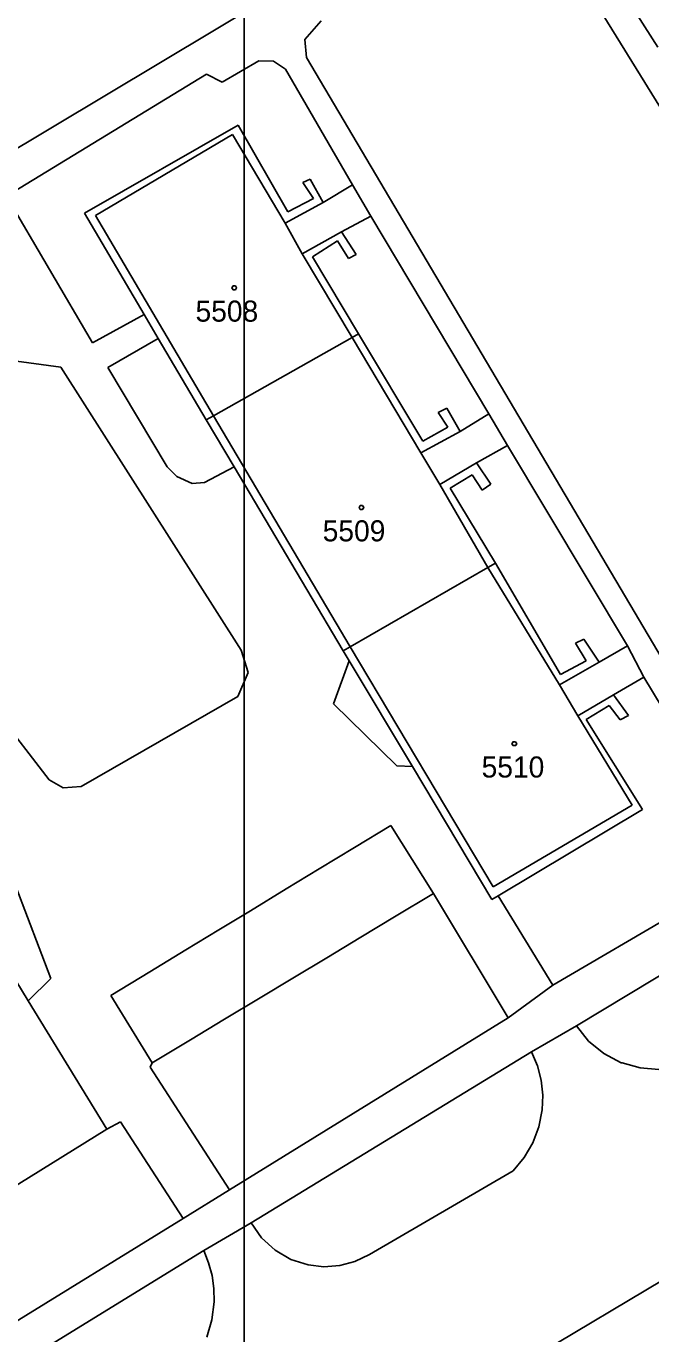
# Model space of a CAD drawing. Extents: x -263587 to -261993, y -1238795 to -1236748.
# Drawn here: x -263008.6 to -262961.1, y -1237443 to -1237343.7 of the extents above; entities that cross this region are included whole.
import ezdxf

# ---------------------------------------------------------------- set-up
doc = ezdxf.new("R2010")
doc.units = 0
doc.layers.add('Vrstva 1', color=7, linetype='Continuous')
doc.layers.add('Vrstva 51', color=7, linetype='Continuous')

msp = doc.modelspace()

# ---------------------------------------------------------------- linework, layer by layer
at = {"layer": 'Vrstva 1'}
for p, q in [((-262969.49, -1237335.2), (-262932.48, -1237395.21)), ((-263042.6, -1237372.96), (-262982.3, -1237336.84)), ((-262987.41, -1237344.72), (-262986.18, -1237343.32)), ((-262960.62, -1237345.3), (-262962.19, -1237342.85)), ((-262962.19, -1237342.85), (-262960.62, -1237345.3)), ((-262987.29, -1237346.1), (-262987.41, -1237344.72)), ((-262990.92, -1237346.35), (-262993.69, -1237347.98)), ((-262989.79, -1237346.37), (-262990.92, -1237346.35)), ((-262988.88, -1237346.97), (-262989.79, -1237346.37)), ((-262951.55, -1237406.53), (-262987.29, -1237346.1)), ((-262994.89, -1237347.35), (-263010.07, -1237356.63)), ((-262993.69, -1237347.98), (-262994.89, -1237347.35)), ((-262983.81, -1237355.75), (-262988.88, -1237346.97)), ((-263004.15, -1237357.92), (-262992.49, -1237351.22)), ((-262992.49, -1237351.22), (-263004.15, -1237357.92)), ((-262992.49, -1237351.22), (-262988.71, -1237357.81)), ((-262988.71, -1237357.81), (-262992.49, -1237351.22)), ((-263003.32, -1237358.1), (-262992.9, -1237351.94)), ((-262992.9, -1237351.94), (-262988.92, -1237358.66)), ((-262987.58, -1237355.59), (-262987.02, -1237355.32)), ((-262987.02, -1237355.32), (-262987.58, -1237355.59)), ((-262987.02, -1237355.32), (-262986.03, -1237357.1)), ((-262986.03, -1237357.1), (-262987.02, -1237355.32)), ((-262986.77, -1237356.8), (-262987.58, -1237355.59)), ((-262987.58, -1237355.59), (-262986.77, -1237356.8)), ((-262986.03, -1237357.1), (-262983.81, -1237355.75)), ((-262983.81, -1237355.75), (-262986.03, -1237357.1)), ((-262983.81, -1237355.75), (-262982.4, -1237358.15)), ((-262982.4, -1237358.15), (-262983.81, -1237355.75)), ((-263003.53, -1237367.75), (-263010.07, -1237356.63)), ((-262986.03, -1237357.1), (-262988.92, -1237358.66)), ((-262988.71, -1237357.81), (-262986.77, -1237356.8)), ((-262986.77, -1237356.8), (-262988.71, -1237357.81)), ((-262999.63, -1237365.6), (-263004.15, -1237357.92)), ((-263004.15, -1237357.92), (-262999.63, -1237365.6)), ((-262994.36, -1237373.3), (-263003.32, -1237358.1)), ((-262982.4, -1237358.15), (-262984.63, -1237359.32)), ((-262984.63, -1237359.32), (-262982.4, -1237358.15)), ((-262982.4, -1237358.15), (-262973.44, -1237373.14)), ((-262988.92, -1237358.66), (-262987.61, -1237361)), ((-262987.61, -1237361), (-262984.63, -1237359.32)), ((-262984.63, -1237359.32), (-262983.52, -1237361.04)), ((-262983.52, -1237361.04), (-262984.63, -1237359.32)), ((-262984.95, -1237360.02), (-262986.83, -1237361.22)), ((-262986.83, -1237361.22), (-262984.95, -1237360.02)), ((-262984.11, -1237361.36), (-262984.95, -1237360.02)), ((-262984.95, -1237360.02), (-262984.11, -1237361.36)), ((-262983.83, -1237367.35), (-262987.61, -1237361)), ((-262986.83, -1237361.22), (-262983.35, -1237367.08)), ((-262983.35, -1237367.08), (-262986.83, -1237361.22)), ((-262983.52, -1237361.04), (-262984.11, -1237361.36)), ((-262984.11, -1237361.36), (-262983.52, -1237361.04)), ((-262999.63, -1237365.6), (-263003.53, -1237367.75)), ((-262998.56, -1237367.42), (-262999.63, -1237365.6)), ((-262999.63, -1237365.6), (-262998.56, -1237367.42)), ((-262983.83, -1237367.35), (-262983.35, -1237367.08)), ((-262983.35, -1237367.08), (-262983.83, -1237367.35)), ((-262983.35, -1237367.08), (-262978.46, -1237375.22)), ((-262978.46, -1237375.22), (-262983.35, -1237367.08)), ((-263005.94, -1237369.6), (-263019.33, -1237367.8)), ((-262998.56, -1237367.42), (-263002.37, -1237369.64)), ((-262994.9, -1237373.61), (-262998.56, -1237367.42)), ((-262998.56, -1237367.42), (-262994.9, -1237373.61)), ((-262994.36, -1237373.3), (-262983.83, -1237367.35)), ((-262983.83, -1237367.35), (-262994.36, -1237373.3)), ((-262983.83, -1237367.35), (-262978.61, -1237376.12)), ((-262992.25, -1237391.09), (-263005.94, -1237369.6)), ((-263002.37, -1237369.64), (-262997.86, -1237377.17)), ((-262994.9, -1237373.61), (-262994.36, -1237373.3)), ((-262994.36, -1237373.3), (-262994.9, -1237373.61)), ((-262994.36, -1237373.3), (-262983.98, -1237390.83)), ((-262977.29, -1237373.05), (-262976.63, -1237372.71)), ((-262976.63, -1237372.71), (-262977.29, -1237373.05)), ((-262976.56, -1237374.17), (-262977.29, -1237373.05)), ((-262977.29, -1237373.05), (-262976.56, -1237374.17)), ((-262976.63, -1237372.71), (-262975.62, -1237374.48)), ((-262975.62, -1237374.48), (-262976.63, -1237372.71)), ((-262975.62, -1237374.48), (-262973.44, -1237373.14)), ((-262973.44, -1237373.14), (-262975.62, -1237374.48)), ((-262973.44, -1237373.14), (-262972.02, -1237375.56)), ((-262972.02, -1237375.56), (-262973.44, -1237373.14)), ((-262992.79, -1237377.16), (-262994.9, -1237373.61)), ((-262994.9, -1237373.61), (-262992.79, -1237377.16)), ((-262978.46, -1237375.22), (-262976.56, -1237374.17)), ((-262976.56, -1237374.17), (-262978.46, -1237375.22)), ((-262975.62, -1237374.48), (-262978.61, -1237376.12)), ((-262978.61, -1237376.12), (-262977.16, -1237378.5)), ((-262972.02, -1237375.56), (-262974.39, -1237376.86)), ((-262974.39, -1237376.86), (-262972.02, -1237375.56)), ((-262972.02, -1237375.56), (-262962.93, -1237390.75)), ((-262997.86, -1237377.17), (-262997.15, -1237377.9)), ((-262995.03, -1237378.35), (-262992.79, -1237377.16)), ((-262984.51, -1237391.13), (-262992.79, -1237377.16)), ((-262992.79, -1237377.16), (-262984.51, -1237391.13)), ((-262977.16, -1237378.5), (-262974.39, -1237376.86)), ((-262974.39, -1237376.86), (-262973.29, -1237378.49)), ((-262973.29, -1237378.49), (-262974.39, -1237376.86)), ((-262997.15, -1237377.9), (-262995.97, -1237378.43)), ((-262974.72, -1237377.78), (-262976.39, -1237378.79)), ((-262976.39, -1237378.79), (-262974.72, -1237377.78)), ((-262973.95, -1237378.94), (-262974.72, -1237377.78)), ((-262974.72, -1237377.78), (-262973.95, -1237378.94)), ((-262995.97, -1237378.43), (-262995.03, -1237378.35)), ((-262973.52, -1237384.81), (-262977.16, -1237378.5)), ((-262976.39, -1237378.79), (-262972.94, -1237384.48)), ((-262972.94, -1237384.48), (-262976.39, -1237378.79)), ((-262973.29, -1237378.49), (-262973.95, -1237378.94)), ((-262973.95, -1237378.94), (-262973.29, -1237378.49)), ((-263023.05, -1237379.95), (-263006.82, -1237400.93)), ((-262973.52, -1237384.81), (-262983.98, -1237390.83)), ((-262983.98, -1237390.83), (-262973.52, -1237384.81)), ((-262972.94, -1237384.48), (-262973.52, -1237384.81)), ((-262973.52, -1237384.81), (-262972.94, -1237384.48)), ((-262973.52, -1237384.81), (-262968.08, -1237393.71)), ((-262972.94, -1237384.48), (-262968.01, -1237392.94)), ((-262968.01, -1237392.94), (-262972.94, -1237384.48)), ((-262915.31, -1237388.58), (-262966.8, -1237419.62)), ((-262991.72, -1237392.78), (-262992.25, -1237391.09)), ((-262983.98, -1237390.83), (-262984.51, -1237391.13)), ((-262984.51, -1237391.13), (-262983.98, -1237390.83)), ((-262984.06, -1237391.89), (-262984.51, -1237391.13)), ((-262984.51, -1237391.13), (-262984.06, -1237391.89)), ((-262983.98, -1237390.83), (-262973.12, -1237409.06)), ((-262966.87, -1237390.55), (-262966.24, -1237390.26)), ((-262966.24, -1237390.26), (-262966.87, -1237390.55)), ((-262966.06, -1237391.89), (-262966.87, -1237390.55)), ((-262966.87, -1237390.55), (-262966.06, -1237391.89)), ((-262966.24, -1237390.26), (-262965.06, -1237391.99)), ((-262965.06, -1237391.99), (-262966.24, -1237390.26)), ((-262965.06, -1237391.99), (-262962.93, -1237390.75)), ((-262962.93, -1237390.75), (-262965.06, -1237391.99)), ((-262962.93, -1237390.75), (-262961.67, -1237393.13)), ((-262961.67, -1237393.13), (-262962.93, -1237390.75)), ((-262984.06, -1237391.89), (-262985.24, -1237395.16)), ((-262979.25, -1237399.93), (-262984.06, -1237391.89)), ((-262984.06, -1237391.89), (-262979.25, -1237399.93)), ((-262965.06, -1237391.99), (-262968.08, -1237393.71)), ((-262968.01, -1237392.94), (-262966.06, -1237391.89)), ((-262966.06, -1237391.89), (-262968.01, -1237392.94)), ((-262992.51, -1237394.6), (-262991.72, -1237392.78)), ((-262961.67, -1237393.13), (-262963.99, -1237394.48)), ((-262963.99, -1237394.48), (-262961.67, -1237393.13)), ((-262961.67, -1237393.13), (-262953.09, -1237407.45)), ((-262968.08, -1237393.71), (-262966.68, -1237396.08)), ((-263004.39, -1237401.45), (-262992.51, -1237394.6)), ((-262966.68, -1237396.08), (-262963.99, -1237394.48)), ((-262963.99, -1237394.48), (-262962.84, -1237396.04)), ((-262962.84, -1237396.04), (-262963.99, -1237394.48)), ((-262985.24, -1237395.16), (-262980.44, -1237399.86)), ((-262962.56, -1237402.85), (-262966.68, -1237396.08)), ((-262964.3, -1237395.28), (-262966.05, -1237396.36)), ((-262966.05, -1237396.36), (-262964.3, -1237395.28)), ((-262963.48, -1237396.38), (-262964.3, -1237395.28)), ((-262964.3, -1237395.28), (-262963.48, -1237396.38)), ((-262962.84, -1237396.04), (-262963.48, -1237396.38)), ((-262963.48, -1237396.38), (-262962.84, -1237396.04)), ((-262966.05, -1237396.36), (-262961.78, -1237403.18)), ((-262961.78, -1237403.18), (-262966.05, -1237396.36)), ((-262980.44, -1237399.86), (-262979.25, -1237399.93)), ((-262973.21, -1237410.02), (-262979.25, -1237399.93)), ((-262979.25, -1237399.93), (-262973.21, -1237410.02)), ((-263006.82, -1237400.93), (-263005.78, -1237401.55)), ((-263005.78, -1237401.55), (-263004.39, -1237401.45)), ((-262973.12, -1237409.06), (-262962.56, -1237402.85)), ((-262961.78, -1237403.18), (-262972.75, -1237409.74)), ((-262972.75, -1237409.74), (-262961.78, -1237403.18)), ((-262980.9, -1237404.4), (-262983.65, -1237406.07)), ((-262977.66, -1237409.56), (-262980.9, -1237404.4)), ((-262983.65, -1237406.07), (-262986.33, -1237407.7)), ((-262986.33, -1237407.7), (-262988.84, -1237409.22)), ((-262968.59, -1237416.53), (-262953.09, -1237407.45)), ((-262953.09, -1237407.45), (-262968.59, -1237416.53)), ((-263009.36, -1237409.04), (-263006.7, -1237416.01)), ((-262988.84, -1237409.22), (-262991.54, -1237410.87)), ((-262980.61, -1237411.34), (-262977.66, -1237409.56)), ((-262977.66, -1237409.56), (-262971.99, -1237419)), ((-262972.75, -1237409.74), (-262973.21, -1237410.02)), ((-262973.21, -1237410.02), (-262972.75, -1237409.74)), ((-262972.75, -1237409.74), (-262968.59, -1237416.53)), ((-262991.54, -1237410.87), (-262993.94, -1237412.32)), ((-263008.42, -1237417.72), (-263012.14, -1237411.64)), ((-262983.16, -1237412.88), (-262980.61, -1237411.34)), ((-262993.94, -1237412.32), (-262996.46, -1237413.85)), ((-262985.75, -1237414.44), (-262983.16, -1237412.88)), ((-262996.46, -1237413.85), (-262999.18, -1237415.51)), ((-262988.34, -1237415.99), (-262985.75, -1237414.44)), ((-262999.18, -1237415.51), (-263002.15, -1237417.32)), ((-262990.82, -1237417.49), (-262988.34, -1237415.99)), ((-263006.7, -1237416.01), (-263008.42, -1237417.72)), ((-262971.99, -1237419), (-262968.59, -1237416.53)), ((-262968.59, -1237416.53), (-262971.99, -1237419)), ((-263002.46, -1237427.46), (-263008.42, -1237417.72)), ((-263002.15, -1237417.32), (-262999, -1237422.41)), ((-262993.51, -1237419.11), (-262990.82, -1237417.49)), ((-262996.1, -1237420.67), (-262993.51, -1237419.11)), ((-262993.13, -1237432.05), (-262971.99, -1237419)), ((-262971.99, -1237419), (-262993.13, -1237432.05)), ((-262966.8, -1237419.62), (-262970.2, -1237421.59)), ((-262970.2, -1237421.59), (-262966.8, -1237419.62)), ((-262965.87, -1237420.78), (-262966.8, -1237419.62)), ((-262966.8, -1237419.62), (-262965.87, -1237420.78)), ((-262999, -1237422.41), (-262996.1, -1237420.67)), ((-262964.71, -1237421.72), (-262965.87, -1237420.78)), ((-262965.87, -1237420.78), (-262964.71, -1237421.72)), ((-262970.2, -1237421.59), (-262991.5, -1237434.57)), ((-262970.2, -1237421.59), (-262969.76, -1237422.64)), ((-262969.76, -1237422.64), (-262970.2, -1237421.59)), ((-262963.39, -1237422.41), (-262964.71, -1237421.72)), ((-262964.71, -1237421.72), (-262963.39, -1237422.41)), ((-262999, -1237422.41), (-262999.16, -1237422.74)), ((-262999.16, -1237422.74), (-262993.13, -1237432.05)), ((-262969.76, -1237422.64), (-262969.47, -1237423.74)), ((-262969.47, -1237423.74), (-262969.76, -1237422.64)), ((-262963.33, -1237422.43), (-262963.39, -1237422.41)), ((-262963.39, -1237422.41), (-262963.33, -1237422.43)), ((-262961.96, -1237422.81), (-262963.33, -1237422.43)), ((-262963.33, -1237422.43), (-262961.96, -1237422.81)), ((-262960.54, -1237422.92), (-262961.96, -1237422.81)), ((-262961.96, -1237422.81), (-262960.54, -1237422.92)), ((-262969.47, -1237423.74), (-262969.35, -1237424.87)), ((-262969.35, -1237424.87), (-262969.47, -1237423.74)), ((-262969.35, -1237424.87), (-262969.39, -1237426)), ((-262969.39, -1237426), (-262969.35, -1237424.87)), ((-263001.42, -1237426.9), (-263002.46, -1237427.46)), ((-262996.66, -1237434.23), (-263001.42, -1237426.9)), ((-262969.39, -1237426), (-262969.64, -1237427.28)), ((-262969.64, -1237427.28), (-262969.39, -1237426)), ((-263012.7, -1237433.8), (-263002.46, -1237427.46)), ((-262969.64, -1237427.28), (-262970.11, -1237428.49)), ((-262970.11, -1237428.49), (-262969.64, -1237427.28)), ((-262970.11, -1237428.49), (-262970.77, -1237429.61)), ((-262970.77, -1237429.61), (-262970.11, -1237428.49)), ((-262970.77, -1237429.61), (-262971.6, -1237430.61)), ((-262971.6, -1237430.61), (-262970.77, -1237429.61)), ((-262971.6, -1237430.61), (-262982.52, -1237436.98)), ((-262982.52, -1237436.98), (-262971.6, -1237430.61)), ((-262996.66, -1237434.23), (-262993.13, -1237432.05)), ((-262993.13, -1237432.05), (-262996.66, -1237434.23)), ((-262976.5, -1237448.59), (-262949.5, -1237432.51)), ((-262949.5, -1237432.51), (-262976.5, -1237448.59)), ((-263010.45, -1237442.74), (-262996.66, -1237434.23)), ((-262996.66, -1237434.23), (-263010.45, -1237442.74)), ((-262991.5, -1237434.57), (-262995.1, -1237436.67)), ((-262995.1, -1237436.67), (-262991.5, -1237434.57)), ((-262990.7, -1237435.7), (-262991.5, -1237434.57)), ((-262991.5, -1237434.57), (-262990.7, -1237435.7)), ((-262989.68, -1237436.64), (-262990.7, -1237435.7)), ((-262990.7, -1237435.7), (-262989.68, -1237436.64)), ((-262995.1, -1237436.67), (-263047.25, -1237468.74)), ((-262995.1, -1237436.67), (-262994.73, -1237437.6)), ((-262994.73, -1237437.6), (-262995.1, -1237436.67)), ((-262988.49, -1237437.34), (-262989.68, -1237436.64)), ((-262989.68, -1237436.64), (-262988.49, -1237437.34)), ((-262994.73, -1237437.6), (-262994.46, -1237438.57)), ((-262994.46, -1237438.57), (-262994.73, -1237437.6)), ((-262987.17, -1237437.76), (-262988.49, -1237437.34)), ((-262988.49, -1237437.34), (-262987.17, -1237437.76)), ((-262985.97, -1237437.9), (-262987.17, -1237437.76)), ((-262987.17, -1237437.76), (-262985.97, -1237437.9)), ((-262984.77, -1237437.81), (-262985.97, -1237437.9)), ((-262985.97, -1237437.9), (-262984.77, -1237437.81)), ((-262983.61, -1237437.5), (-262984.77, -1237437.81)), ((-262984.77, -1237437.81), (-262983.61, -1237437.5)), ((-262982.52, -1237436.98), (-262983.61, -1237437.5)), ((-262983.61, -1237437.5), (-262982.52, -1237436.98)), ((-262994.46, -1237438.57), (-262994.32, -1237439.56)), ((-262994.32, -1237439.56), (-262994.46, -1237438.57)), ((-262994.32, -1237439.56), (-262994.3, -1237440.56)), ((-262994.3, -1237440.56), (-262994.32, -1237439.56)), ((-262994.3, -1237440.56), (-262994.47, -1237441.93)), ((-262994.47, -1237441.93), (-262994.3, -1237440.56)), ((-262994.47, -1237441.93), (-262994.87, -1237443.25)), ((-262994.87, -1237443.25), (-262994.47, -1237441.93))]:
    msp.add_line(p, q, dxfattribs=at)
for points in [[(-262992.69, -1237363.43), (-262992.6, -1237363.58), (-262992.69, -1237363.73), (-262992.87, -1237363.73), (-262992.96, -1237363.58), (-262992.87, -1237363.43)], [(-262983.03, -1237380.11), (-262982.94, -1237380.26), (-262983.03, -1237380.41), (-262983.21, -1237380.41), (-262983.3, -1237380.26), (-262983.21, -1237380.11)], [(-262971.42, -1237398.04), (-262971.33, -1237398.19), (-262971.42, -1237398.34), (-262971.6, -1237398.34), (-262971.69, -1237398.19), (-262971.6, -1237398.04)]]:
    msp.add_lwpolyline(points, close=True, dxfattribs=at)
at = {"layer": 'Vrstva 51'}
msp.add_lwpolyline([(-262992.03, -1237088.09), (-262695.03, -1237088.09), (-262695.03, -1238768.09), (-262992.03, -1238768.09)], close=True, dxfattribs=at)

# ---------------------------------------------------------------- texts
at = {"layer": 'Vrstva 1'}
for s, p in [('5508', (-262995.717, -1237366.15)), ('5509', (-262986.063, -1237382.83)), ('5510', (-262973.994, -1237400.76))]:
    msp.add_text(s, height=1.6, dxfattribs=at).set_placement(p)

doc.saveas('drawing.dxf')
